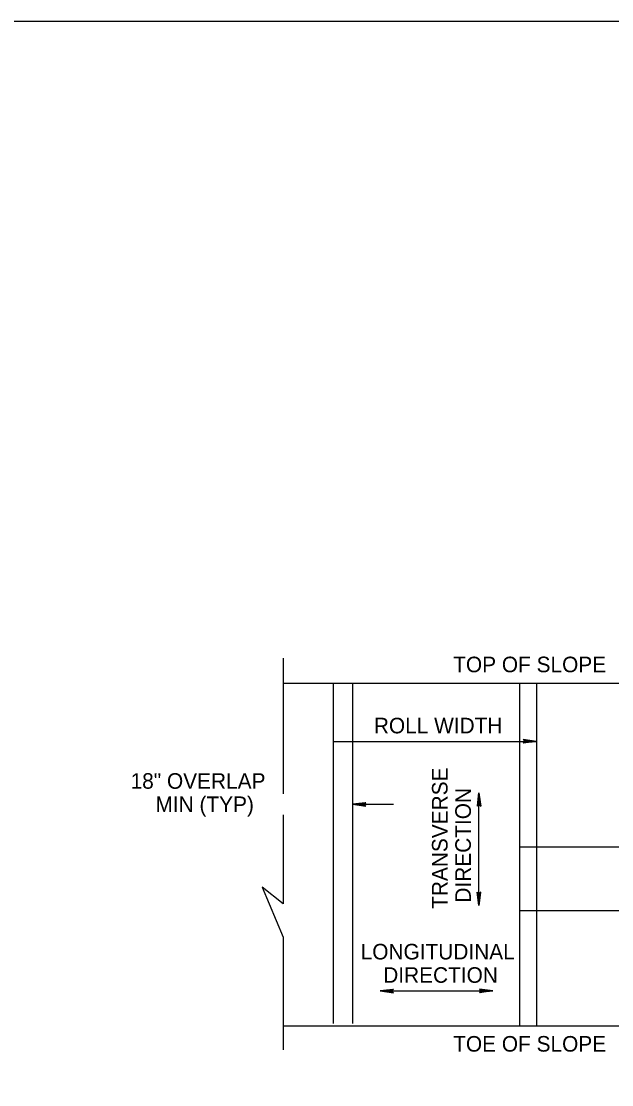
# Model space of a CAD drawing. Extents: x 2189223 to 2190097, y 563994 to 564498.
# Drawn here: x 2189702.6 to 2189792.8, y 564243.4 to 564405.9 of the extents above; entities that cross this region are included whole.
import ezdxf

# ---------------------------------------------------------------- set-up
doc = ezdxf.new("R2010")
doc.units = 0
doc.layers.add('Default', color=7, linetype='Continuous')
doc.layers.add('Old_Level_2', color=7, linetype='Continuous')

msp = doc.modelspace()

# ---------------------------------------------------------------- linework, layer by layer
at = {"layer": 'Default'}
for p, q in [((2189742.58, 564308.59), (2189742.58, 564287.86)), ((2189817.07, 564304.71), (2189742.58, 564304.71)), ((2189750.23, 564304.71), (2189750.23, 564252.75)), ((2189753.15, 564304.71), (2189753.15, 564252.75)), ((2189778.68, 564304.71), (2189778.68, 564252.36)), ((2189781.29, 564304.71), (2189781.29, 564252.36)), ((2189750.23, 564295.86), (2189781.29, 564295.86)), ((2189772.49, 564270.76), (2189772.49, 564287.99)), ((2189753.15, 564286.24), (2189759.43, 564286.24)), ((2189742.57, 564284.62), (2189742.57, 564271.02)), ((2189809.42, 564279.7), (2189778.68, 564279.7)), ((2189742.57, 564271.02), (2189739.38, 564273.56)), ((2189739.38, 564273.56), (2189742.57, 564265.95)), ((2189781.29, 564269.95), (2189778.68, 564269.95)), ((2189809.42, 564269.95), (2189781.29, 564269.95)), ((2189742.57, 564265.95), (2189742.57, 564248.68)), ((2189757.39, 564257.71), (2189774.61, 564257.71)), ((2189742.58, 564252.36), (2189817.07, 564252.36))]:
    msp.add_line(p, q, dxfattribs=at)
msp.add_lwpolyline([(2189347.77, 564405.93), (2189877.15, 564405.93), (2189877.15, 564038.89), (2189347.77, 564038.89)], close=True, dxfattribs=at)
at = {"layer": 'Old_Level_2'}
for p, q in [((2189781.29, 564295.86), (2189779.24, 564296.14)), ((2189779.24, 564296.14), (2189779.5, 564295.86)), ((2189781.29, 564295.86), (2189779.24, 564295.59)), ((2189779.5, 564295.86), (2189779.24, 564295.59)), ((2189779.28, 564296.1), (2189781.29, 564295.86)), ((2189781.29, 564295.86), (2189779.28, 564295.63)), ((2189781.29, 564295.86), (2189779.32, 564296.06)), ((2189779.32, 564295.67), (2189781.29, 564295.86)), ((2189779.35, 564296.02), (2189781.29, 564295.86)), ((2189781.29, 564295.86), (2189779.35, 564295.71)), ((2189781.29, 564295.86), (2189779.39, 564295.98)), ((2189779.39, 564295.75), (2189781.29, 564295.86)), ((2189779.43, 564295.94), (2189781.29, 564295.86)), ((2189781.29, 564295.86), (2189779.43, 564295.79)), ((2189781.29, 564295.86), (2189779.47, 564295.91)), ((2189779.47, 564295.83), (2189781.29, 564295.86)), ((2189779.5, 564295.86), (2189781.29, 564295.86)), ((2189772.49, 564287.99), (2189772.21, 564285.94)), ((2189772.25, 564285.98), (2189772.49, 564287.99)), ((2189772.49, 564287.99), (2189772.29, 564286.02)), ((2189772.33, 564286.05), (2189772.49, 564287.99)), ((2189772.49, 564287.99), (2189772.37, 564286.09)), ((2189772.41, 564286.13), (2189772.49, 564287.99)), ((2189772.49, 564287.99), (2189772.45, 564286.17)), ((2189772.49, 564287.99), (2189772.76, 564285.94)), ((2189772.49, 564286.2), (2189772.49, 564287.99)), ((2189772.53, 564286.17), (2189772.49, 564287.99)), ((2189772.49, 564287.99), (2189772.56, 564286.13)), ((2189772.6, 564286.09), (2189772.49, 564287.99)), ((2189772.49, 564287.99), (2189772.65, 564286.05)), ((2189772.69, 564286.02), (2189772.49, 564287.99)), ((2189772.49, 564287.99), (2189772.72, 564285.98)), ((2189753.15, 564286.24), (2189755.2, 564286.52)), ((2189753.15, 564286.24), (2189755.16, 564286.48)), ((2189755.12, 564286.44), (2189753.15, 564286.24)), ((2189753.15, 564286.24), (2189755.08, 564286.4)), ((2189755.04, 564286.36), (2189753.15, 564286.24)), ((2189753.15, 564286.24), (2189755.01, 564286.32)), ((2189754.97, 564286.28), (2189753.15, 564286.24)), ((2189753.15, 564286.24), (2189755.2, 564285.96)), ((2189755.16, 564286), (2189753.15, 564286.24)), ((2189753.15, 564286.24), (2189755.12, 564286.04)), ((2189755.08, 564286.08), (2189753.15, 564286.24)), ((2189753.15, 564286.24), (2189755.04, 564286.12)), ((2189755.01, 564286.16), (2189753.15, 564286.24)), ((2189753.15, 564286.24), (2189754.97, 564286.2)), ((2189754.93, 564286.24), (2189753.15, 564286.24)), ((2189754.93, 564286.24), (2189755.2, 564286.52)), ((2189755.2, 564285.96), (2189754.93, 564286.24)), ((2189772.21, 564285.94), (2189772.49, 564286.2)), ((2189772.49, 564286.2), (2189772.76, 564285.94)), ((2189772.49, 564270.76), (2189772.21, 564272.81)), ((2189772.49, 564272.55), (2189772.21, 564272.81)), ((2189772.49, 564270.76), (2189772.25, 564272.77)), ((2189772.29, 564272.73), (2189772.49, 564270.76)), ((2189772.49, 564270.76), (2189772.33, 564272.7)), ((2189772.37, 564272.66), (2189772.49, 564270.76)), ((2189772.49, 564270.76), (2189772.41, 564272.62)), ((2189772.45, 564272.58), (2189772.49, 564270.76)), ((2189772.49, 564270.76), (2189772.76, 564272.81)), ((2189772.76, 564272.81), (2189772.49, 564272.55)), ((2189772.73, 564272.77), (2189772.49, 564270.76)), ((2189772.49, 564270.76), (2189772.69, 564272.73)), ((2189772.65, 564272.7), (2189772.49, 564270.76)), ((2189772.49, 564270.76), (2189772.6, 564272.66)), ((2189772.57, 564272.62), (2189772.49, 564270.76)), ((2189772.49, 564270.76), (2189772.53, 564272.58)), ((2189772.49, 564272.55), (2189772.49, 564270.76)), ((2189757.39, 564257.71), (2189759.44, 564257.99)), ((2189757.39, 564257.71), (2189759.4, 564257.95)), ((2189759.36, 564257.91), (2189757.39, 564257.71)), ((2189757.39, 564257.71), (2189759.32, 564257.87)), ((2189759.28, 564257.83), (2189757.39, 564257.71)), ((2189757.39, 564257.71), (2189759.25, 564257.79)), ((2189759.17, 564257.71), (2189759.44, 564257.99)), ((2189774.61, 564257.71), (2189772.57, 564257.99)), ((2189772.57, 564257.99), (2189772.83, 564257.71)), ((2189772.6, 564257.95), (2189774.61, 564257.71)), ((2189774.61, 564257.71), (2189772.64, 564257.91)), ((2189772.68, 564257.87), (2189774.61, 564257.71)), ((2189774.61, 564257.71), (2189772.72, 564257.83)), ((2189772.75, 564257.79), (2189774.61, 564257.71)), ((2189774.61, 564257.71), (2189772.79, 564257.75)), ((2189759.21, 564257.75), (2189757.39, 564257.71)), ((2189757.39, 564257.71), (2189759.44, 564257.44)), ((2189759.4, 564257.47), (2189757.39, 564257.71)), ((2189757.39, 564257.71), (2189759.36, 564257.51)), ((2189759.32, 564257.55), (2189757.39, 564257.71)), ((2189757.39, 564257.71), (2189759.28, 564257.6)), ((2189759.25, 564257.63), (2189757.39, 564257.71)), ((2189757.39, 564257.71), (2189759.21, 564257.67)), ((2189759.17, 564257.71), (2189757.39, 564257.71)), ((2189759.44, 564257.44), (2189759.17, 564257.71)), ((2189774.61, 564257.71), (2189772.57, 564257.44)), ((2189772.83, 564257.71), (2189772.57, 564257.44)), ((2189774.61, 564257.71), (2189772.6, 564257.48)), ((2189772.64, 564257.51), (2189774.61, 564257.71)), ((2189774.61, 564257.71), (2189772.68, 564257.55)), ((2189772.72, 564257.6), (2189774.61, 564257.71)), ((2189774.61, 564257.71), (2189772.75, 564257.64)), ((2189772.79, 564257.67), (2189774.61, 564257.71)), ((2189772.83, 564257.71), (2189774.61, 564257.71))]:
    msp.add_line(p, q, dxfattribs=at)

# ---------------------------------------------------------------- texts
at = {"layer": 'Default'}
for s, height, p in [('TOP OF SLOPE', 2.3822, (2189768.56, 564306.42)), ('ROLL WIDTH', 2.382, (2189756.44, 564297.08)), ('18" OVERLAP', 2.3822, (2189719.27, 564288.61)), ('MIN (TYP)', 2.382, (2189723.07, 564285.05)), ('LONGITUDINAL', 2.3822, (2189754.42, 564262.52)), ('DIRECTION', 2.382, (2189757.87, 564258.95)), ('TOE OF SLOPE', 2.3822, (2189768.56, 564248.43))]:
    msp.add_text(s, height=height, dxfattribs=at).set_placement(p)
for s, p in [('TRANSVERSE', (2189767.7, 564270.26)), ('DIRECTION', (2189771.26, 564271.21))]:
    msp.add_text(s, height=2.382, rotation=90, dxfattribs=at).set_placement(p)

doc.saveas('drawing.dxf')
